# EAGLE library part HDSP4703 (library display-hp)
LED DISPLAY 1-character dot matrix without decimal point
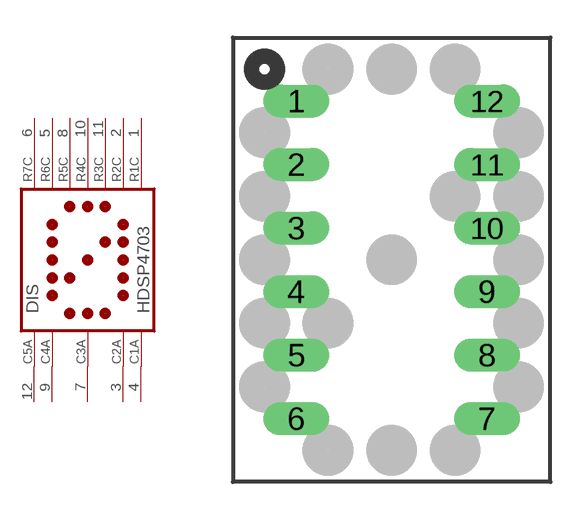
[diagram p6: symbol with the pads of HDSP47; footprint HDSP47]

Designator prefix DIS

## HDSP4703 (OC_FARNELL: unknown; OC_NEWARK: unknown)  [HDSP47]
1  R1C  pas
2  R2C  pas
3  C2A  pas
4  C1A  pas
5  R6C  pas
6  R7C  pas
7  C3A  pas
8  R5C  pas
9  C4A  pas
10  R4C  pas
11  R3C  pas
12  C5A  pas

## Footprint HDSP47 (pad centres in mm)
LED DISPLAY 17-mm 1 character dot matrix without decimal point
drill 0.813 long: 1 -3.81,6.35; 2 -3.81,3.81; 3 -3.81,1.27; 4 -3.81,-1.27; 5 -3.81,-3.81; 6 -3.81,-6.35; 7 3.81,-6.35; 8 3.81,-3.81; 9 3.81,-1.27; 10 3.81,1.27; 11 3.81,3.81; 12 3.81,6.35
